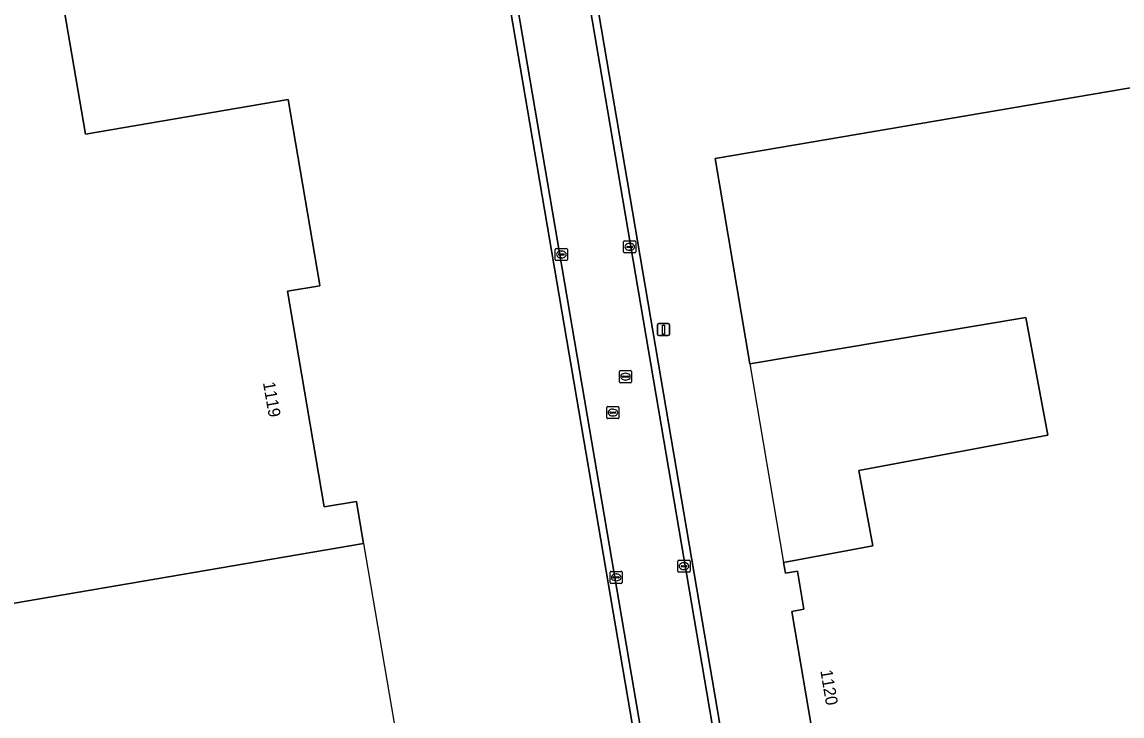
# Model space of a CAD drawing. Extents: x 154324 to 155744, y 382937 to 384188.
# Drawn here: x 154874.3 to 154965.6, y 383397.8 to 383455.3 of the extents above; entities that cross this region are included whole.
import ezdxf

# ---------------------------------------------------------------- set-up
doc = ezdxf.new("R2010")
doc.units = 0
for name, color, linetype in [('IMGEO_Erf', 7, 'Continuous'), ('IMGEO_Grasland_agrarisch', 7, 'Continuous'), ('IMGEO_Hek', 7, 'Continuous'), ('IMGEO_Kolk', 7, 'Continuous'), ('IMGEO_Lichtmast', 7, 'Continuous'), ('IMGEO_Pand', 7, 'Continuous'), ('IMGEO_Pand_nummerreeks', 7, 'Continuous'), ('IMGEO_Pand_overbouw', 7, 'Continuous'), ('IMGEO_Rijbaan_lokaal_gesloten', 7, 'Continuous'), ('IMGEO_Rijbaan_lokaal_open', 7, 'Continuous'), ('IMGEO_Rioolput', 7, 'Continuous')]:
    doc.layers.add(name, color=color, linetype=linetype)

msp = doc.modelspace()

# ---------------------------------------------------------------- linework, layer by layer
at = {"layer": 'IMGEO_Erf'}
msp.add_lwpolyline([(154957.636, 383205.007), (154955.126, 383219.621), (154933.063, 383349.385), (154931.446, 383358.867), (154880.326, 383658.587)], dxfattribs=at)
msp.add_lwpolyline([(154834.619, 383400.461), (154821.718, 383476.24), (154889.716, 383487.815), (154890.443, 383483.587), (154890.304, 383483.564), (154892.766, 383469.145), (154892.803, 383468.928), (154890.043, 383468.457), (154891.058, 383462.645), (154893.935, 383463.15), (154893.976, 383462.908), (154894.602, 383459.232), (154877.774, 383456.368), (154879.542, 383446.048), (154896.359, 383448.912), (154898.955, 383433.672), (154898.99, 383433.466), (154896.309, 383433.01), (154899.362, 383415.11), (154902.045, 383415.555), (154902.077, 383415.363), (154902.623, 383412.072)], close=True, dxfattribs=at)
at = {"layer": 'IMGEO_Grasland_agrarisch'}
msp.add_lwpolyline([(154886.005, 383668.098), (154936.688, 383370.604), (154936.699, 383370.542), (154939.601, 383371.039), (154941.3, 383371.33), (154964.539, 383375.316), (154995.109, 383380.559), (154999.878, 383352.447)], dxfattribs=at)
msp.add_lwpolyline([(154982.688, 383452.666), (154992.885, 383392.595), (154941.984, 383383.986), (154938.166, 383406.445), (154939.152, 383406.613), (154938.627, 383409.767), (154937.644, 383409.605), (154937.479, 383410.489), (154944.895, 383411.887), (154943.721, 383418.118), (154959.415, 383421.076), (154957.574, 383430.84), (154934.692, 383426.973), (154931.812, 383444.014)], close=True, dxfattribs=at)
at = {"layer": 'IMGEO_Hek'}
msp.add_lwpolyline([(154902.623, 383412.072), (154906.674, 383388.272)], dxfattribs=at)
at = {"layer": 'IMGEO_Kolk'}
for p, q in [((154924.208, 383436.262), (154924.208, 383437.114)), ((154924.283, 383437.188), (154925.135, 383437.188)), ((154924.467, 383436.682), (154924.467, 383436.694)), ((154924.51, 383436.731), (154924.908, 383436.731)), ((154924.696, 383436.968), (154924.721, 383436.968)), ((154924.951, 383436.694), (154924.951, 383436.682)), ((154925.209, 383437.114), (154925.209, 383436.262)), ((154918.537, 383435.629), (154918.537, 383436.481)), ((154918.612, 383436.555), (154919.464, 383436.555)), ((154918.796, 383436.049), (154918.796, 383436.061)), ((154919.234, 383436.012), (154918.836, 383436.012)), ((154918.839, 383436.098), (154919.237, 383436.098)), ((154919.048, 383435.775), (154919.023, 383435.775)), ((154919.025, 383436.335), (154919.05, 383436.335)), ((154919.28, 383436.061), (154919.28, 383436.049)), ((154919.538, 383436.481), (154919.538, 383435.629)), ((154925.135, 383436.188), (154924.283, 383436.188)), ((154924.905, 383436.645), (154924.507, 383436.645)), ((154924.719, 383436.408), (154924.694, 383436.408)), ((154919.464, 383435.555), (154918.612, 383435.555)), ((154928.715, 383409.766), (154928.715, 383410.618)), ((154928.79, 383410.692), (154929.642, 383410.692)), ((154928.974, 383410.186), (154928.974, 383410.198)), ((154929.017, 383410.235), (154929.415, 383410.235)), ((154929.203, 383410.472), (154929.228, 383410.472)), ((154929.458, 383410.198), (154929.458, 383410.186)), ((154929.716, 383410.618), (154929.716, 383409.766)), ((154923.088, 383408.839), (154923.088, 383409.691)), ((154923.163, 383409.765), (154924.015, 383409.765)), ((154923.39, 383409.308), (154923.788, 383409.308)), ((154923.576, 383409.545), (154923.601, 383409.545)), ((154924.089, 383409.691), (154924.089, 383408.839)), ((154929.642, 383409.692), (154928.79, 383409.692)), ((154929.412, 383410.149), (154929.014, 383410.149)), ((154929.226, 383409.912), (154929.201, 383409.912)), ((154924.015, 383408.765), (154923.163, 383408.765)), ((154923.347, 383409.259), (154923.347, 383409.271)), ((154923.785, 383409.222), (154923.387, 383409.222)), ((154923.599, 383408.985), (154923.574, 383408.985)), ((154923.831, 383409.271), (154923.831, 383409.259))]:
    msp.add_line(p, q, dxfattribs=at)
for points in [[(154924.208, 383436.262), (154924.208, 383437.114)], [(154924.283, 383437.188), (154925.135, 383437.188)], [(154925.209, 383437.114), (154925.209, 383436.262)], [(154918.537, 383435.629), (154918.537, 383436.481)], [(154918.612, 383436.555), (154919.464, 383436.555)], [(154919.538, 383436.481), (154919.538, 383435.629)], [(154925.135, 383436.188), (154924.283, 383436.188)], [(154919.464, 383435.555), (154918.612, 383435.555)], [(154928.715, 383409.766), (154928.715, 383410.618)], [(154928.79, 383410.692), (154929.642, 383410.692)], [(154929.716, 383410.618), (154929.716, 383409.766)], [(154923.088, 383408.839), (154923.088, 383409.691)], [(154923.163, 383409.765), (154924.015, 383409.765)], [(154924.089, 383409.691), (154924.089, 383408.839)], [(154929.642, 383409.692), (154928.79, 383409.692)], [(154924.015, 383408.765), (154923.163, 383408.765)]]:
    msp.add_lwpolyline(points, dxfattribs=at)
for centre, radius, start, end in [((154924.285, 383437.112), 0.0765, 91.55205, 178.44795), ((154924.285, 383437.112), 0.0765, 91.55205, 178.44795), ((154924.507, 383436.691), 0.0403, 85.87752, 175.75265), ((154924.504, 383436.681), 0.0366, 178.93798, 274.71019), ((154924.908, 383436.688), 0.043, 264.86636, 352.45326), ((154924.912, 383436.693), 0.0386, 1.73085, 96.63898), ((154925.133, 383437.112), 0.0765, 1.55205, 88.44795), ((154925.133, 383437.112), 0.0765, 1.55205, 88.44795), ((154918.614, 383436.479), 0.0765, 91.55205, 178.44795), ((154918.614, 383436.479), 0.0765, 91.55205, 178.44795), ((154918.836, 383436.058), 0.0403, 85.87752, 175.75265), ((154918.833, 383436.048), 0.0366, 178.93798, 274.71019), ((154919.237, 383436.055), 0.043, 264.86636, 352.45326), ((154919.241, 383436.06), 0.0386, 1.73085, 96.63898), ((154919.462, 383436.479), 0.0765, 1.55205, 88.44795), ((154919.462, 383436.479), 0.0765, 1.55205, 88.44795), ((154924.285, 383436.264), 0.0765, 181.55205, 268.44795), ((154924.285, 383436.264), 0.0765, 181.55205, 268.44795), ((154925.133, 383436.264), 0.0765, 271.55205, 358.44795), ((154925.133, 383436.264), 0.0765, 271.55205, 358.44795), ((154918.614, 383435.631), 0.0765, 181.55205, 268.44795), ((154918.614, 383435.631), 0.0765, 181.55205, 268.44795), ((154919.462, 383435.631), 0.0765, 271.55205, 358.44795), ((154919.462, 383435.631), 0.0765, 271.55205, 358.44795), ((154928.792, 383410.616), 0.0765, 91.55205, 178.44795), ((154928.792, 383410.616), 0.0765, 91.55205, 178.44795), ((154929.014, 383410.195), 0.0403, 85.87752, 175.75265), ((154929.419, 383410.197), 0.0386, 1.73085, 96.63898), ((154929.64, 383410.616), 0.0765, 1.55205, 88.44795), ((154929.64, 383410.616), 0.0765, 1.55205, 88.44795), ((154923.165, 383409.689), 0.0765, 91.55205, 178.44795), ((154923.165, 383409.689), 0.0765, 91.55205, 178.44795), ((154923.387, 383409.268), 0.0403, 85.87752, 175.75265), ((154923.792, 383409.27), 0.0386, 1.73085, 96.63898), ((154924.013, 383409.689), 0.0765, 1.55205, 88.44795), ((154924.013, 383409.689), 0.0765, 1.55205, 88.44795), ((154928.792, 383409.768), 0.0765, 181.55205, 268.44795), ((154928.792, 383409.768), 0.0765, 181.55205, 268.44795), ((154929.011, 383410.185), 0.0366, 178.93798, 274.71019), ((154929.415, 383410.192), 0.043, 264.86636, 352.45326), ((154929.64, 383409.768), 0.0765, 271.55205, 358.44795), ((154929.64, 383409.768), 0.0765, 271.55205, 358.44795), ((154923.165, 383408.841), 0.0765, 181.55205, 268.44795), ((154923.165, 383408.841), 0.0765, 181.55205, 268.44795), ((154923.384, 383409.258), 0.0366, 178.93798, 274.71019), ((154923.788, 383409.265), 0.043, 264.86636, 352.45326), ((154924.013, 383408.841), 0.0765, 271.55205, 358.44795), ((154924.013, 383408.841), 0.0765, 271.55205, 358.44795)]:
    msp.add_arc(centre, radius, start, end, dxfattribs=at)
for centre, major_axis, ratio, start_param, end_param in [((154924.695, 383436.688), (-0.387, 0.002), 0.722429, 4.712389, 7.853982), ((154924.72, 383436.688), (-0.39, 0.002), 0.717154, 1.570796, 4.712389), ((154919.024, 383436.055), (-0.387, 0.002), 0.722429, 4.712389, 7.853982), ((154919.049, 383436.055), (-0.39, 0.002), 0.717154, 1.570796, 4.712389), ((154929.202, 383410.192), (-0.387, 0.002), 0.722429, 4.712389, 7.853982), ((154929.227, 383410.192), (-0.39, 0.002), 0.717154, 1.570796, 4.712389), ((154923.575, 383409.265), (-0.387, 0.002), 0.722429, 4.712389, 7.853982), ((154923.6, 383409.265), (-0.39, 0.002), 0.717154, 1.570796, 4.712389)]:
    msp.add_ellipse(centre, major_axis=major_axis, ratio=ratio, start_param=start_param, end_param=end_param, dxfattribs=at)
at = {"layer": 'IMGEO_Lichtmast'}
for p, q in [((154927.114, 383430.322), (154927.904, 383430.322)), ((154927.904, 383430.322), (154927.114, 383430.322)), ((154927.014, 383429.422), (154927.014, 383430.222)), ((154927.014, 383430.222), (154927.014, 383429.422)), ((154928.004, 383430.222), (154928.004, 383429.422)), ((154928.004, 383429.422), (154928.004, 383430.222)), ((154927.904, 383429.322), (154927.114, 383429.322)), ((154927.114, 383429.322), (154927.904, 383429.322))]:
    msp.add_line(p, q, dxfattribs=at)
msp.add_lwpolyline([(154927.434, 383430.197), (154927.584, 383430.197), (154927.584, 383429.447), (154927.434, 383429.447), (154927.434, 383430.197)], dxfattribs=at)
for centre, start, end in [((154927.114, 383430.222), 90, 180), ((154927.114, 383430.222), 90, 180), ((154927.904, 383430.222), 0, 90), ((154927.904, 383430.222), 360, 90), ((154927.114, 383429.422), 180, 270), ((154927.114, 383429.422), 180, 270), ((154927.904, 383429.422), 270, 0), ((154927.904, 383429.422), 270, 0)]:
    msp.add_arc(centre, 0.1, start, end, dxfattribs=at)
at = {"layer": 'IMGEO_Pand'}
for points in [[(154894.602, 383459.232), (154893.976, 383462.908), (154893.935, 383463.15), (154891.058, 383462.645), (154890.043, 383468.457), (154892.803, 383468.928), (154892.766, 383469.145), (154890.304, 383483.564), (154890.443, 383483.587), (154889.716, 383487.815), (154821.718, 383476.24), (154834.619, 383400.461), (154902.623, 383412.072), (154902.077, 383415.363), (154902.045, 383415.555), (154899.362, 383415.11), (154896.309, 383433.01), (154898.99, 383433.466), (154898.955, 383433.672), (154896.359, 383448.912), (154879.542, 383446.048), (154877.774, 383456.368)], [(154982.688, 383452.666), (154931.812, 383444.014), (154934.692, 383426.973), (154957.574, 383430.84), (154959.415, 383421.076), (154943.721, 383418.118), (154944.895, 383411.887), (154937.479, 383410.489), (154937.644, 383409.605), (154938.627, 383409.767), (154939.152, 383406.613), (154938.166, 383406.445), (154941.984, 383383.986), (154992.885, 383392.595)]]:
    msp.add_lwpolyline(points, close=True, dxfattribs=at)
at = {"layer": 'IMGEO_Pand_overbouw'}
msp.add_lwpolyline([(154957.574, 383430.84), (154934.692, 383426.973), (154937.479, 383410.489), (154944.895, 383411.887), (154943.721, 383418.118), (154959.415, 383421.076)], close=True, dxfattribs=at)
at = {"layer": 'IMGEO_Rijbaan_lokaal_gesloten'}
for points in [[(154854.425, 383814.31), (154854.653, 383812.991), (154854.813, 383812.024), (154858.483, 383790.497), (154869.559, 383725.258), (154869.596, 383725.133), (154932.04, 383358.964), (154933.662, 383349.45), (154956.051, 383217.962), (154957.681, 383208.024), (154958.22, 383204.737)], [(154961.836, 383219.4), (154937.891, 383359.922), (154875.734, 383724.688)]]:
    msp.add_lwpolyline(points, dxfattribs=at)
at = {"layer": 'IMGEO_Rijbaan_lokaal_open'}
for points in [[(154859.21, 383821.776), (154860.592, 383813.666), (154872.994, 383740.868), (154875.261, 383727.607), (154875.734, 383724.688), (154937.891, 383359.922), (154938.491, 383360.02), (154937.698, 383364.674), (154936.71, 383370.477), (154936.699, 383370.542), (154936.688, 383370.604), (154886.005, 383668.098)], [(154853.936, 383813.593), (154856.176, 383800.396), (154857.871, 383790.412), (154868.954, 383725.158), (154878.393, 383669.904), (154880.297, 383658.755), (154880.326, 383658.587), (154931.446, 383358.867), (154932.04, 383358.964), (154869.596, 383725.133), (154869.559, 383725.258), (154858.483, 383790.497), (154854.813, 383812.024), (154854.653, 383812.991), (154854.425, 383814.31)]]:
    msp.add_lwpolyline(points, dxfattribs=at)
at = {"layer": 'IMGEO_Rioolput'}
for p, q in [((154923.86, 383425.493), (154923.86, 383426.345)), ((154923.935, 383426.419), (154924.787, 383426.419)), ((154924.119, 383425.913), (154924.119, 383425.925)), ((154924.557, 383425.876), (154924.159, 383425.876)), ((154924.162, 383425.962), (154924.56, 383425.962)), ((154924.348, 383426.199), (154924.373, 383426.199)), ((154924.603, 383425.925), (154924.603, 383425.913)), ((154924.861, 383426.345), (154924.861, 383425.493)), ((154924.787, 383425.419), (154923.935, 383425.419)), ((154924.371, 383425.639), (154924.346, 383425.639)), ((154922.814, 383422.511), (154922.814, 383423.363)), ((154922.889, 383423.437), (154923.741, 383423.437)), ((154923.116, 383422.98), (154923.514, 383422.98)), ((154923.302, 383423.217), (154923.327, 383423.217)), ((154923.815, 383423.363), (154923.815, 383422.511)), ((154923.741, 383422.437), (154922.889, 383422.437)), ((154923.073, 383422.931), (154923.073, 383422.943)), ((154923.511, 383422.894), (154923.113, 383422.894)), ((154923.325, 383422.657), (154923.3, 383422.657)), ((154923.557, 383422.943), (154923.557, 383422.931))]:
    msp.add_line(p, q, dxfattribs=at)
for points in [[(154923.86, 383425.493), (154923.86, 383426.345)], [(154923.935, 383426.419), (154924.787, 383426.419)], [(154924.861, 383426.345), (154924.861, 383425.493)], [(154924.787, 383425.419), (154923.935, 383425.419)], [(154922.814, 383422.511), (154922.814, 383423.363)], [(154922.889, 383423.437), (154923.741, 383423.437)], [(154923.815, 383423.363), (154923.815, 383422.511)], [(154923.741, 383422.437), (154922.889, 383422.437)]]:
    msp.add_lwpolyline(points, dxfattribs=at)
for centre, radius, start, end in [((154923.937, 383426.343), 0.0765, 91.55205, 178.44795), ((154923.937, 383426.343), 0.0765, 91.55205, 178.44795), ((154924.159, 383425.922), 0.0403, 85.87752, 175.75265), ((154924.156, 383425.912), 0.0366, 178.93798, 274.71019), ((154924.56, 383425.919), 0.043, 264.86636, 352.45326), ((154924.564, 383425.924), 0.0386, 1.73085, 96.63898), ((154924.785, 383426.343), 0.0765, 1.55205, 88.44795), ((154924.785, 383426.343), 0.0765, 1.55205, 88.44795), ((154923.937, 383425.495), 0.0765, 181.55205, 268.44795), ((154923.937, 383425.495), 0.0765, 181.55205, 268.44795), ((154924.785, 383425.495), 0.0765, 271.55205, 358.44795), ((154924.785, 383425.495), 0.0765, 271.55205, 358.44795), ((154922.891, 383423.361), 0.0765, 91.55205, 178.44795), ((154922.891, 383423.361), 0.0765, 91.55205, 178.44795), ((154923.113, 383422.94), 0.0403, 85.87752, 175.75265), ((154923.518, 383422.942), 0.0386, 1.73085, 96.63898), ((154923.739, 383423.361), 0.0765, 1.55205, 88.44795), ((154923.739, 383423.361), 0.0765, 1.55205, 88.44795), ((154922.891, 383422.513), 0.0765, 181.55205, 268.44795), ((154922.891, 383422.513), 0.0765, 181.55205, 268.44795), ((154923.11, 383422.93), 0.0366, 178.93798, 274.71019), ((154923.514, 383422.937), 0.043, 264.86636, 352.45326), ((154923.739, 383422.513), 0.0765, 271.55205, 358.44795), ((154923.739, 383422.513), 0.0765, 271.55205, 358.44795)]:
    msp.add_arc(centre, radius, start, end, dxfattribs=at)
for centre, major_axis, ratio, start_param, end_param in [((154924.347, 383425.919), (-0.387, 0.002), 0.722429, 4.712389, 7.853982), ((154924.372, 383425.919), (-0.39, 0.002), 0.717154, 1.570796, 4.712389), ((154923.301, 383422.937), (-0.387, 0.002), 0.722429, 4.712389, 7.853982), ((154923.326, 383422.937), (-0.39, 0.002), 0.717154, 1.570796, 4.712389)]:
    msp.add_ellipse(centre, major_axis=major_axis, ratio=ratio, start_param=start_param, end_param=end_param, dxfattribs=at)

# ---------------------------------------------------------------- texts
at = {"layer": 'IMGEO_Pand_nummerreeks'}
for s, rotation, p in [('1119', 279.90878, (154894.265, 383425.417)), ('1120', 279.6484, (154940.525, 383401.521))]:
    msp.add_text(s, height=1, rotation=rotation, dxfattribs=at).set_placement(p)

doc.saveas('drawing.dxf')
